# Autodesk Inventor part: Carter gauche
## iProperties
Shininess: 64.0
Length Units: 11269
Angle Units: 11279
Time Units: 11290
Mass Units: 11283
Length Display Precision: 3
Angle Display Precision: 2
Compacted: True
Part Number: Carter gauche
Document SubType Name: Modeling
Created: 2003-05
Material: Delrin - Noir
Designer: Philippe
Density: 0.0
Volumn: 0.0
Area: 0.0
PropertySet Name: Model Information
Control State: 0
Master: False
Checked Out: False
Author: Philippe
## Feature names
1. Collerette de centrage [Extrusion]
2. Perçage1 [Hole]
3. Perçage2 [Hole]
4. Perçage3 [Hole]
5. Perçage4 [Hole]
6. Extrusion2
7. Corps dérivé1 [Tagging]
